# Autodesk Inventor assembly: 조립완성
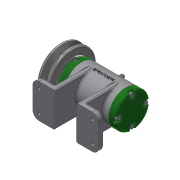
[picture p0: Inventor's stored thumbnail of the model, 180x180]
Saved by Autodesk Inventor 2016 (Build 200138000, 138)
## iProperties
Created: 2017-02
Part Number: 조립완성
Material: 일반
Document SubType Name: Assembly
Designer: CAMTIC
Author: CAMTIC
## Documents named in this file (16)
- C:\Users\CAMTIC\Desktop\470207V1013\조립완성.iam
- C:\Users\CAMTIC\Desktop\470207V1013\본체.ipt
- C:\Users\CAMTIC\Desktop\470207V1013\V벨트풀리.ipt
- C:\Users\CAMTIC\Desktop\470207V1013\너트 M 8.ipt
- C:\Users\CAMTIC\Desktop\470207V1013\니플 M 6 x 0.75.ipt
- C:\Users\CAMTIC\Desktop\470207V1013\뒤커버.ipt
- C:\Users\CAMTIC\Desktop\470207V1013\베어링 15 x 32 x 9.ipt
- C:\Users\CAMTIC\Desktop\470207V1013\볼트 M 6 x 8.ipt
- C:\Users\CAMTIC\Desktop\470207V1013\볼트 M4 x 12.ipt
- C:\Users\CAMTIC\Desktop\470207V1013\스프링와셔 8.ipt
- C:\Users\CAMTIC\Desktop\470207V1013\앞커버.ipt
- C:\Users\CAMTIC\Desktop\470207V1013\오일 실 15 25 7.ipt
- C:\Users\CAMTIC\Desktop\470207V1013\와셔 6x11.5.ipt
- C:\Users\CAMTIC\Desktop\470207V1013\와셔 8x17.ipt
- C:\Users\CAMTIC\Desktop\470207V1013\축.ipt
- C:\Users\CAMTIC\Desktop\470207V1013\키 3 x 3 x 12.ipt
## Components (11 placed, 3 different names)
1. V벨트풀리:1
2. KS B 2023 6002 - 15 x 32 x 9:1
3. KS B 2023 6002 - 15 x 32 x 9:2
4. ISO 4762 M4 x 12:2
5. ISO 4762 M4 x 12:3
6. ISO 4762 M4 x 12:4
7. ISO 4762 M4 x 12:5
8. ISO 4762 M4 x 12:1
9. ISO 4762 M4 x 12:6
10. ISO 4762 M4 x 12:7
11. ISO 4762 M4 x 12:8
